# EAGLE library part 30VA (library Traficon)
TRANSFORMER 1 primary windig + 1 primary winding with tap, 2 secondary windings, core ring
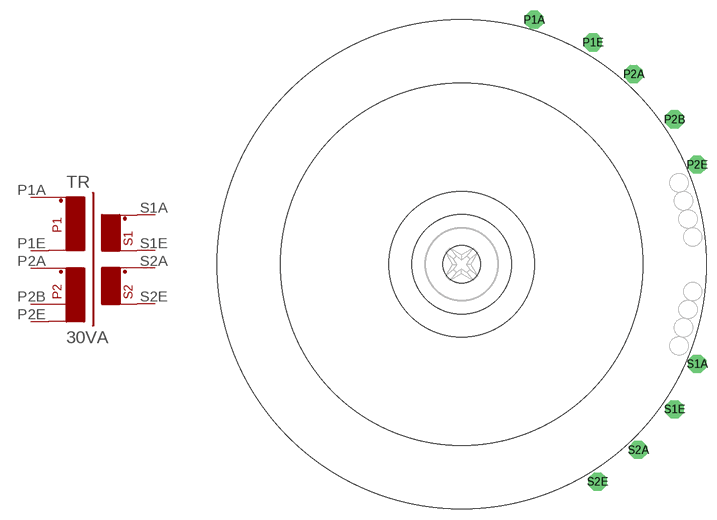
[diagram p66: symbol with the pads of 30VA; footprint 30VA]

Designator prefix TR

## 30VA  [30VA]
P1A  P1A  pas
P1E  P1E  pas
P2A  P2A  pas
P2B  P2B  pas
P2E  P2E  pas
S1A  S1A  pas
S1E  S1E  pas
S2A  S2A  pas
S2E  S2E  pas

## Footprint 30VA (pad centres in mm)
TRANSFORMER 1 primary windig + 1 primary winding with tap, 2 secondary windings, core ring
drill 1.016 pad 2.54 octagon: P1A 10.16,34.29; P1E 18.415,31.115; P2A 24.13,26.67; P2B 29.845,20.32; P2E 33.02,13.97; S1A 33.02,-13.97; S1E 29.845,-20.32; S2A 24.765,-26.035; S2E 19.05,-30.48
hole 5.309 at 0,0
